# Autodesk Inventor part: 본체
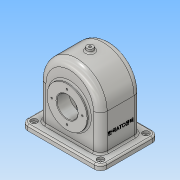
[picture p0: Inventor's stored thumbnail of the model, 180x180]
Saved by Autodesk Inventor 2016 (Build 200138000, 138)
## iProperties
Created: 2018-08
Part Number: 본체
Material: 알루미늄 6061
Document SubType Name: Modeling
Designer: Administrator
Density: 2.7 g/cm^3
Appearance: 알루미늄 - 평지
Mass: 1098.75 g
Surface Area: 1182.68 cm^2
Volume: 406.945 cm^3
Author: Administrator
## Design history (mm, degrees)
sketch "스케치1"
  geometry: L1 (-75, 55)-(75, 55); L2 (75, 55)-(75, -55); L3 (75, -55)-(-75, -55); L4 (-75, -55)-(-75, 55); L5 (-75, 55)-(75, -55); L6 (75, 55)-(-75, -55); 1 further point
  constraints: 12 end point, 2 midpoint, 2 parallel, 1 horizontal, 1 perpendicular
  dimensions: "d0" = 150 distance of L2.end L3.end; "d1" = 110 distance of L1.end L2.end
extrude "돌출1" new body sketch "스케치1" distance "d2" = 10; taper "d3" = 0 deg
sketch "스케치2"
  geometry: L1 (-75, 10)-(75, 10) reference; L2 (58, 10)-(58, 78); L3 (-58, 10)-(-58, 78); L4 (121.024, 78)-(-192.022, 78); L5 (-75, 0)-(75, 0) reference; L6 (0, 153.171)-(0, -76.626); L7 (58, 10)-(-58, 10); A1 r 58 centre (0, 78) between (58, 78) and (-58, 78); 2 further points
  constraints: 10 end point, 6 point on line, 3 vertical, 2 point on circle, 2 tangent, 1 centre point, 1 collinear, 1 horizontal, 1 midpoint
  dimensions: "d4" = 58 radius of A1; "d5" = 78 distance between parallel lines of L5 L4
extrude "돌출2" join sketch "스케치2" stored distance "d6" = 77; taper "d7" = 0 deg
sketch "스케치3"
  geometry: L1 (-123.728, 65)-(217.975, 65); L2 (75, 0)-(-75, 0) reference; L3 (0, 179.208)-(0, -151.352); C1 r 38 at (0, 65); 2 further points
  constraints: 4 end point, 3 point on line, 1 centre point, 1 horizontal, 1 midpoint, 1 vertical
  dimensions: "d8" = 65 distance between parallel lines of L2 L1; "d9" = 76 diameter of C1
extrude "돌출3" join sketch "스케치3" distance "d10" = 5; taper "d11" = 0 deg
sketch "스케치4"
  geometry: L1 (174.798, -65)-(-207.761, -65); L2 (0, -181.53)-(0, 146.709); L3 (-75, 0)-(75, 0) reference; C1 r 38 at (0, -65); 2 further points
  constraints: 4 end point, 3 point on line, 1 centre point, 1 horizontal, 1 midpoint, 1 vertical
  dimensions: "d12" = 65 distance between parallel lines of L3 L1; "d13" = 76 diameter of C1
extrude "돌출4" join sketch "스케치4" distance "d14" = 10; taper "d15" = 0 deg
sketch "스케치5"
  geometry: 1 further point
sketch "스케치6"
  geometry: L1 (0, 177.04)-(0, -124.567); L2 (131.64, 78)-(-188.676, 78); L3 (75, 0)-(-75, 0) reference; L4 (52, 78)-(52, 0); L5 (-52, 78)-(-52, 0); L6 (52, 0)-(-52, 0); A1 r 52 centre (0, 78) between (52, 78) and (-52, 78); 1 further point
  constraints: 10 end point, 6 point on line, 2 horizontal, 2 point on circle, 2 tangent, 2 vertical, 1 centre point, 1 perpendicular
  dimensions: "d16" = 78 distance between parallel lines of L3 L2; "d17" = 52 radius of A1
extrude "돌출5" cut sketch "스케치6" stored distance "d18" = 67; taper "d19" = 0 deg
sketch "스케치8"
  geometry: C1 r 20 at (0, 0); 1 further point
  constraints: 1 centre point
  dimensions: "d27" = 40 diameter of C1
extrude "돌출7" cut sketch "스케치8" stored distance "d28" = 67; taper "d29" = 0 deg
node "작업 평면1"
sketch "스케치9"
  geometry: C1 r 6 at (0, 0); 1 further point
  constraints: 1 centre point, 1 coincident
  dimensions: "d31" = 12 diameter of C1
extrude "돌출8" join sketch "스케치9" stored distance "d32" = 67; taper "d33" = 5 deg
hole "구멍1" diameter "d36" = 4.459; stored, may be unused: countersink angle "d40" = 90 deg, drill point angle "d42" = 118 deg; dims "d34" = 10, "d35" = 10, "d37" = 10, "d38" = 4, "d39" = 2, "d41" = 12.8
fillet "모깎기1" dims "d43" = 8
fillet "모깎기2" dims "d44" = 13
fillet "모깎기3" dims "d45" = 12
sketch "스케치10"
  geometry: C1 r 6 at (-63, -43); A1 r 12 centre (-63, -43) between (-75, -43) and (-63, -55) reference; 1 further point
  constraints: 1 centre point, 1 coincident
  dimensions: "d46" = 12 diameter of C1
extrude "돌출9" cut sketch "스케치10" distance "d47" = 4; taper "d48" = 0 deg
hole "구멍2" diameter "d51" = 5; stored, may be unused: countersink angle "d55" = 90 deg, drill point angle "d57" = 118 deg; dims "d49" = 10, "d50" = 10, "d52" = 10, "d53" = 4, "d54" = 2, "d56" = 12.8
sketch "스케치12" dims "d69" = 58
  geometry: L1 (0, -89.739)-(0, 102.17); C1 r 20 at (0, 0) reference; 3 further points
  constraints: 2 end point, 1 coincident, 1 point on line, 1 vertical, 1 vertical alignment, 2 other
hole "구멍4" sketch "스케치12" at (0, -29) diameter "d70" = 3.242; stored, may be unused: countersink angle "d74" = 90 deg, drill point angle "d76" = 118 deg; dims "d71" = 8, "d72" = 4, "d73" = 2, "d75" = 10
sketch "스케치13"
  geometry: L1 (78, 68.5)-(78, -17.5) reference; L2 (0, -13)-(68, -13) reference; 2 further points
  constraints: 1 other
  dimensions: "d80" = 40 distance from line of L1 point (38, 25.5); "d81" = 38.5 distance from line of point (38, 25.5) L2
feature "엠보싱1" sketch "스케치13" dims "d82" = 0.5, "d83" = 0
chamfer "모따기1" distance "d84" = 1; stored, may be unused: second distance "d85" = 2, angle "d86" = 45 deg
fillet "모깎기4" dims "d87" = 3
fillet "모깎기5" dims "d88" = 3
sketch "스케치14"
  geometry: L1 (-78.544, 65)-(117.623, 65); L2 (-33.5, 104.747)-(-19.5, 93); L3 (-19.5, 93)-(-19.5, 65); L4 (-33.5, 130)-(-33.5, 78); L5 (-33.5, 104.747)-(-33.5, 65); L6 (-43.5, 103)-(-43.5, 27); 1 further point
  constraints: 12 end point, 3 point on line, 1 horizontal, 1 perpendicular
  dimensions: "d89" = 50 deg angle of L3 L2; "d90" = 28 distance of L3.end L2.end; "d91" = 24 distance between parallel lines of L6 L3
revolve "회전1" sketch "스케치14" stored, may be unused: angle "d92" = 90 deg
sketch "스케치15"
  geometry: C1 r 20 at (0, 0); 1 further point
  constraints: 1 centre point
  dimensions: "d93" = 40 diameter of C1
extrude "돌출10" cut sketch "스케치15" stored distance "d94" = 4; taper "d95" = 0 deg
chamfer "모따기2" distance "d96" = 1; stored, may be unused: second distance "d97" = 2, angle "d98" = 45 deg
sketch "스케치16" dims "d99" = 58
  geometry: L1 (0, 104.485)-(0, -157.339); 3 further points
  constraints: 2 end point, 1 point on line, 1 vertical, 1 vertical alignment, 2 other
hole "구멍5" sketch "스케치16" at (0, 29) diameter "d100" = 3.242; stored, may be unused: countersink angle "d104" = 90 deg, drill point angle "d106" = 118 deg; dims "d101" = 8, "d102" = 4, "d103" = 2, "d105" = 10
node "솔리드1"
mirror "대칭1"
mirror "대칭2"
pattern_circular "원형 패턴2" dims angle "d78" = 360 deg
pattern_circular "원형 패턴3" dims angle "d108" = 360 deg
other parameters: "d30" = -142
